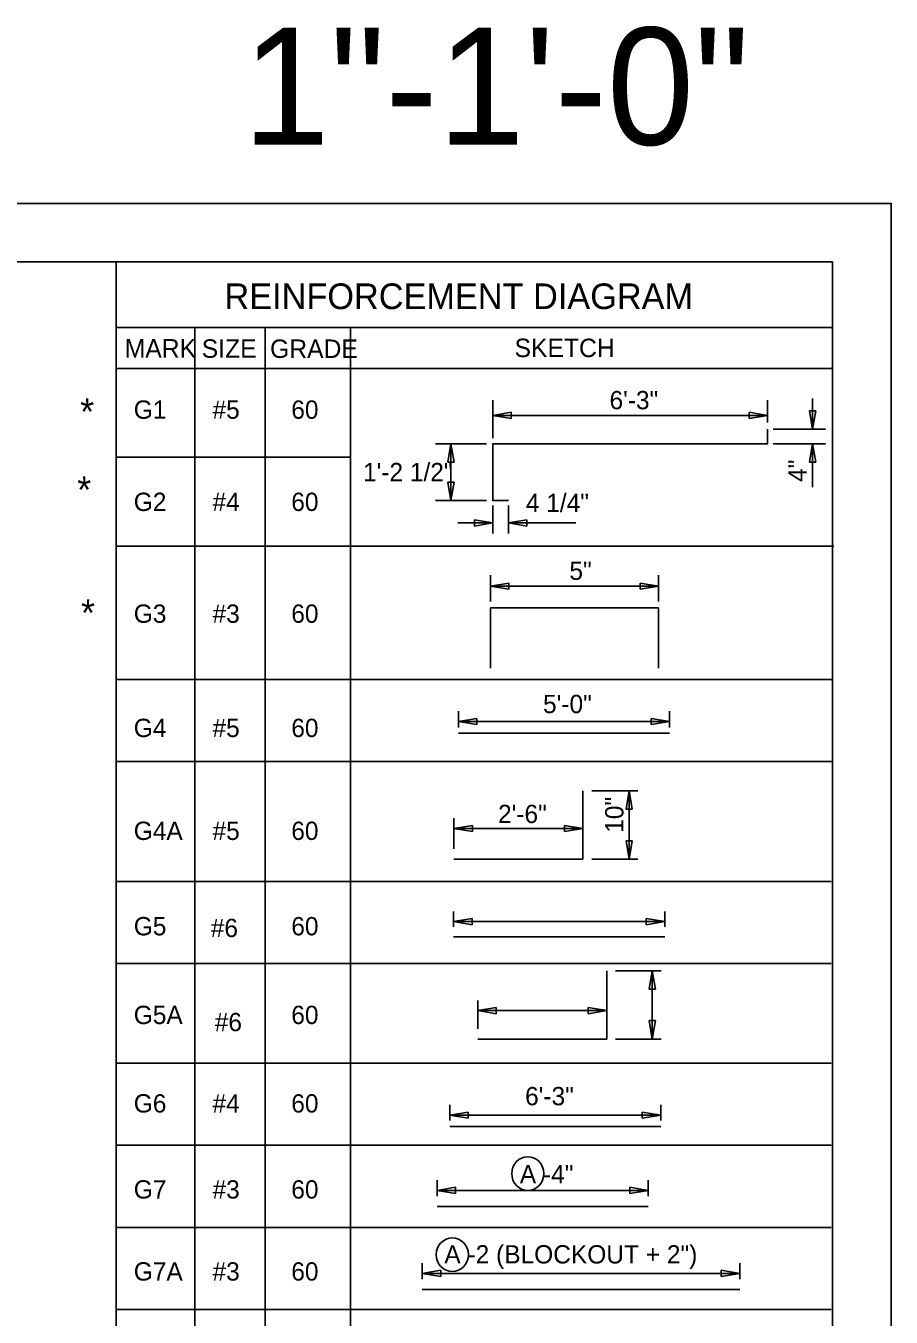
# Model space of a CAD drawing. Extents: x 0 to 34, y 0 to 23.5.
# Drawn here: x 26.62 to 34, y 12.5 to 23.51 of the extents above; entities that cross this region are included whole.
import ezdxf

# ---------------------------------------------------------------- set-up
doc = ezdxf.new("R2010")
doc.units = 0
for name, color, linetype in [('BORDER_ANNO_Cutsheet', 7, 'Continuous'), ('BRDG_ANNO_Anno-Sheet', 7, 'Continuous'), ('BRDG_ANNO_General-Notes', 7, 'Continuous'), ('BRDG_BASE_Obj-Line', 7, 'Continuous'), ('BRDG_BASE_Rebar', 7, 'Continuous'), ('Default', 7, 'Continuous')]:
    doc.layers.add(name, color=color, linetype=linetype)

# ---------------------------------------------------------------- blocks, each defined once
blk = doc.blocks.new('TERM')
at = {"layer": 'Default'}
for p, q in [((-1.6, -0.27), (-1.6, 0.27)), ((-1.6, 0.27), (0, 0)), ((0, 0), (-1.6, -0.27))]:
    blk.add_line(p, q, dxfattribs=at)

msp = doc.modelspace()

# ---------------------------------------------------------------- linework, layer by layer
at = {"layer": 'BORDER_ANNO_Cutsheet'}
msp.add_lwpolyline([(0, 22), (34, 22), (34, 0), (0, 0)], close=True, dxfattribs=at)
at = {"layer": 'BRDG_ANNO_Anno-Sheet'}
msp.add_lwpolyline([(1.5, 21.5), (33.5, 21.5), (33.5, 0.5), (1.5, 0.5)], close=True, dxfattribs=at)
at = {"layer": 'BRDG_ANNO_General-Notes'}
for p, q in [((30.601, 19.995), (30.601, 20.32)), ((32.945, 20.129), (32.945, 20.32)), ((33.329, 20.073), (33.329, 20.336)), ((30.601, 20.191), (30.759, 20.217)), ((30.601, 20.191), (32.945, 20.191)), ((30.759, 20.165), (30.601, 20.191)), ((30.759, 20.217), (30.759, 20.165)), ((32.788, 20.165), (32.788, 20.217)), ((32.788, 20.217), (32.945, 20.191)), ((32.945, 20.191), (32.788, 20.165)), ((33.303, 20.231), (33.356, 20.231)), ((33.329, 20.073), (33.303, 20.231)), ((33.356, 20.231), (33.329, 20.073)), ((32.992, 20.073), (33.439, 20.073)), ((30.547, 19.948), (30.112, 19.948)), ((30.218, 19.791), (30.244, 19.948)), ((30.244, 19.464), (30.244, 19.948)), ((30.244, 19.948), (30.271, 19.791)), ((32.992, 19.948), (33.439, 19.948)), ((33.303, 19.791), (33.329, 19.948)), ((33.329, 19.577), (33.329, 19.948)), ((33.329, 19.948), (33.356, 19.791)), ((30.271, 19.791), (30.218, 19.791)), ((33.356, 19.791), (33.303, 19.791)), ((30.218, 19.621), (30.271, 19.621)), ((30.244, 19.464), (30.218, 19.621)), ((30.271, 19.621), (30.244, 19.464)), ((30.547, 19.464), (30.112, 19.464)), ((30.601, 19.422), (30.601, 19.184)), ((30.734, 19.422), (30.734, 19.184)), ((30.444, 19.246), (30.444, 19.299)), ((30.444, 19.299), (30.601, 19.273)), ((30.734, 19.273), (30.892, 19.299)), ((30.892, 19.299), (30.892, 19.246)), ((30.601, 19.273), (30.302, 19.273)), ((30.601, 19.273), (30.444, 19.246)), ((31.311, 19.273), (30.734, 19.273)), ((30.892, 19.246), (30.734, 19.273)), ((30.583, 18.603), (30.583, 18.826)), ((32.016, 18.733), (30.583, 18.733)), ((32.016, 18.603), (32.016, 18.826)), ((30.309, 17.528), (30.309, 17.666)), ((32.11, 17.528), (32.11, 17.666)), ((30.309, 17.578), (30.466, 17.605)), ((30.309, 17.578), (32.11, 17.578)), ((30.466, 17.552), (30.309, 17.578)), ((30.466, 17.605), (30.466, 17.552)), ((31.952, 17.552), (31.952, 17.605)), ((31.952, 17.605), (32.11, 17.578)), ((32.11, 17.578), (31.952, 17.552)), ((31.445, 16.987), (31.839, 16.987)), ((31.738, 16.83), (31.764, 16.987)), ((31.764, 16.987), (31.764, 16.403)), ((31.764, 16.987), (31.791, 16.83)), ((30.27, 16.491), (30.27, 16.754)), ((31.791, 16.83), (31.738, 16.83)), ((30.27, 16.666), (30.427, 16.692)), ((30.27, 16.666), (31.37, 16.666)), ((30.427, 16.64), (30.27, 16.666)), ((30.427, 16.692), (30.427, 16.64)), ((31.213, 16.64), (31.213, 16.692)), ((31.213, 16.692), (31.37, 16.666)), ((31.37, 16.666), (31.213, 16.64)), ((31.738, 16.561), (31.791, 16.561)), ((31.764, 16.403), (31.738, 16.561)), ((31.791, 16.561), (31.764, 16.403)), ((31.445, 16.403), (31.839, 16.403)), ((30.267, 15.827), (30.267, 15.958)), ((30.267, 15.871), (30.424, 15.897)), ((30.267, 15.871), (32.068, 15.871)), ((30.424, 15.844), (30.267, 15.871)), ((30.424, 15.897), (30.424, 15.844)), ((31.91, 15.844), (31.91, 15.897)), ((31.91, 15.897), (32.068, 15.871)), ((32.068, 15.871), (31.91, 15.844)), ((32.068, 15.827), (32.068, 15.958)), ((31.648, 15.452), (32.037, 15.452)), ((31.936, 15.294), (31.962, 15.452)), ((31.962, 15.452), (31.962, 14.868)), ((31.962, 15.452), (31.988, 15.294)), ((31.988, 15.294), (31.936, 15.294)), ((30.473, 14.956), (30.473, 15.199)), ((30.473, 15.112), (30.63, 15.138)), ((30.473, 15.112), (31.573, 15.112)), ((30.63, 15.085), (30.473, 15.112)), ((30.63, 15.138), (30.63, 15.085)), ((31.416, 15.085), (31.416, 15.138)), ((31.416, 15.138), (31.573, 15.112)), ((31.573, 15.112), (31.416, 15.085)), ((31.573, 14.956), (31.573, 15.199)), ((31.936, 15.026), (31.988, 15.026)), ((31.962, 14.868), (31.936, 15.026)), ((31.988, 15.026), (31.962, 14.868)), ((31.648, 14.868), (32.037, 14.868)), ((30.234, 14.174), (30.234, 14.307)), ((30.234, 14.22), (30.392, 14.246)), ((30.234, 14.22), (32.035, 14.22)), ((30.392, 14.194), (30.234, 14.22)), ((30.392, 14.246), (30.392, 14.194)), ((31.877, 14.194), (31.877, 14.246)), ((31.877, 14.246), (32.035, 14.22)), ((32.035, 14.22), (31.877, 14.194)), ((32.035, 14.174), (32.035, 14.307)), ((30.126, 13.527), (30.126, 13.666)), ((31.927, 13.527), (31.927, 13.666)), ((30.126, 13.578), (30.283, 13.604)), ((30.126, 13.578), (31.927, 13.578)), ((30.283, 13.552), (30.126, 13.578)), ((30.283, 13.604), (30.283, 13.552)), ((31.769, 13.552), (31.769, 13.604)), ((31.769, 13.604), (31.927, 13.578)), ((31.927, 13.578), (31.769, 13.552)), ((30, 12.819), (30, 12.957)), ((30, 12.869), (30.157, 12.896)), ((30.157, 12.896), (30.157, 12.843)), ((32.551, 12.843), (32.551, 12.896)), ((32.551, 12.896), (32.708, 12.869)), ((32.708, 12.819), (32.708, 12.957)), ((30, 12.869), (32.708, 12.869)), ((30.157, 12.843), (30, 12.869)), ((32.708, 12.869), (32.551, 12.843))]:
    msp.add_line(p, q, dxfattribs=at)
for centre in [(30.9, 13.721), (30.256, 13.029)]:
    msp.add_ellipse(centre, major_axis=(0, 0.144), ratio=0.952381, dxfattribs=at)
at = {"layer": 'BRDG_BASE_Obj-Line'}
for p, q in [((27.387, 21.499), (27.387, 7.095)), ((27.387, 20.941), (33.506, 20.941)), ((28.06, 20.941), (28.06, 7.095)), ((28.66, 20.941), (28.66, 7.095)), ((29.386, 20.941), (29.386, 7.095)), ((27.387, 20.591), (33.5, 20.591)), ((28.059, 20.308), (28.059, 10.039)), ((27.387, 19.835), (29.386, 19.835)), ((27.387, 19.076), (33.512, 19.076)), ((27.387, 17.938), (33.494, 17.938)), ((27.387, 17.237), (33.506, 17.237)), ((27.387, 16.214), (33.488, 16.214)), ((27.387, 15.513), (33.488, 15.513)), ((27.387, 14.663), (33.488, 14.663)), ((27.387, 13.963), (33.488, 13.963)), ((27.387, 13.262), (33.488, 13.262)), ((27.387, 12.562), (33.488, 12.562))]:
    msp.add_line(p, q, dxfattribs=at)
at = {"layer": 'BRDG_BASE_Rebar'}
for p, q in [((30.583, 18.548), (32.016, 18.548)), ((30.583, 18.548), (30.583, 18.033)), ((32.016, 18.548), (32.016, 18.033)), ((30.309, 17.48), (32.11, 17.48)), ((31.37, 16.403), (31.37, 16.987)), ((30.27, 16.403), (31.37, 16.403)), ((30.267, 15.74), (32.068, 15.74)), ((31.573, 14.868), (31.573, 15.452)), ((30.473, 14.868), (31.573, 14.868)), ((30.234, 14.123), (32.035, 14.123)), ((30.126, 13.44), (31.927, 13.44)), ((30, 12.731), (32.708, 12.731))]:
    msp.add_line(p, q, dxfattribs=at)
msp.add_lwpolyline([(30.734, 19.464), (30.601, 19.464), (30.601, 19.948), (32.945, 19.948), (32.945, 20.073)], dxfattribs=at)

# ---------------------------------------------------------------- block references
at = {"layer": 'BRDG_ANNO_General-Notes', "xscale": 0.09765625, "yscale": 0.0976318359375, "rotation": 180}
msp.add_blockref('TERM', (30.583, 18.733), dxfattribs=at)
at = {"layer": 'BRDG_ANNO_General-Notes', "xscale": 0.09765625, "yscale": 0.0976318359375}
msp.add_blockref('TERM', (32.016, 18.733), dxfattribs=at)

# ---------------------------------------------------------------- texts
at = {"layer": 'BRDG_ANNO_Anno-Sheet'}
msp.add_text('1"-1\'-0"', height=1, dxfattribs=at).set_placement((28.467, 22.5))
at = {"layer": 'BRDG_ANNO_General-Notes'}
for s, height, p in [('REINFORCEMENT DIAGRAM', 0.21875, (28.312, 21.098)), ('MARK', 0.1576, (27.461, 20.684)), ('SIZE', 0.1576, (28.118, 20.682)), ('GRADE', 0.1575, (28.701, 20.681)), ('SKETCH', 0.1575, (30.787, 20.688)), ('6\'-3"', 0.1562, (31.597, 20.243)), ('*', 0.229, (27.081, 20.108)), ('G1', 0.1562, (27.538, 20.162)), ('#5', 0.1562, (28.21, 20.162)), ('60', 0.1562, (28.882, 20.162)), ('1\'-2 1/2"', 0.1562, (29.494, 19.629)), ('*', 0.229, (27.056, 19.442)), ('G2', 0.1562, (27.538, 19.375)), ('#4', 0.1562, (28.21, 19.375)), ('60', 0.1562, (28.882, 19.375)), ('4 1/4"', 0.1562, (30.883, 19.366)), ('5"', 0.1562, (31.255, 18.787)), ('*', 0.229, (27.088, 18.392)), ('G3', 0.1562, (27.538, 18.421)), ('#3', 0.1562, (28.21, 18.421)), ('60', 0.1562, (28.882, 18.421)), ('5\'-0"', 0.1562, (31.03, 17.65)), ('G4', 0.1562, (27.538, 17.446)), ('#5', 0.1562, (28.21, 17.446)), ('60', 0.1562, (28.882, 17.446)), ('2\'-6"', 0.1562, (30.646, 16.712)), ('G4A', 0.1562, (27.538, 16.568)), ('#5', 0.1562, (28.21, 16.568)), ('60', 0.1562, (28.882, 16.568)), ('G5', 0.1562, (27.538, 15.754)), ('#6', 0.1562, (28.195, 15.739)), ('60', 0.1562, (28.882, 15.754)), ('G5A', 0.1562, (27.538, 14.997)), ('60', 0.1562, (28.882, 14.997)), ('#6', 0.1562, (28.229, 14.936)), ('6\'-3"', 0.1562, (30.877, 14.304)), ('G6', 0.1562, (27.538, 14.242)), ('#4', 0.1562, (28.21, 14.242)), ('60', 0.1562, (28.882, 14.242)), ('A -4"', 0.1562, (30.832, 13.638)), ('G7', 0.1562, (27.538, 13.508)), ('#3', 0.1562, (28.21, 13.508)), ('60', 0.1562, (28.882, 13.508)), ('A -2 (BLOCKOUT + 2")', 0.15625, (30.188, 12.954)), ('G7A', 0.1562, (27.538, 12.808)), ('#3', 0.1562, (28.21, 12.808)), ('60', 0.1562, (28.882, 12.808))]:
    msp.add_text(s, height=height, dxfattribs=at).set_placement(p)
for s, p in [('4"', (33.278, 19.623)), ('10"', (31.716, 16.629))]:
    msp.add_text(s, height=0.1562, rotation=90, dxfattribs=at).set_placement(p)

doc.saveas('drawing.dxf')
